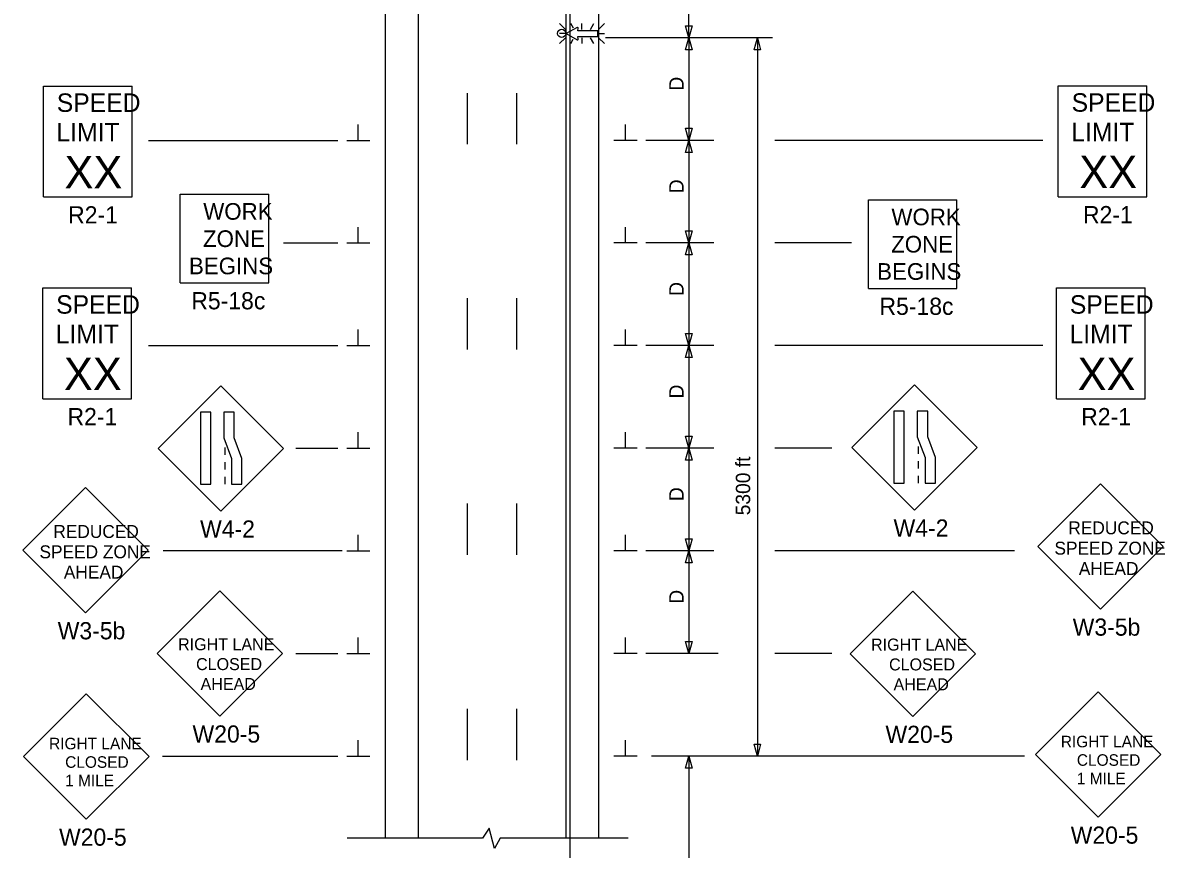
# Model space of a CAD drawing. Extents: x 16247 to 18479, y 5687 to 6964.
# Drawn here: x 16736 to 17293, y 6228 to 6630 of the extents above; entities that cross this region are included whole.
import ezdxf

# ---------------------------------------------------------------- set-up
doc = ezdxf.new("R2010")
doc.units = 0
for name, color, linetype in [('ALI_LEGAL_EX', 7, 'Continuous'), ('PAVT_EDGE_EX', 7, 'Continuous'), ('TRAFFIC_SIGNS_PR', 7, 'Continuous'), ('TYPICAL_TEXT_DIMEN_PR', 7, 'Continuous')]:
    doc.layers.add(name, color=color, linetype=linetype)

msp = doc.modelspace()

# ---------------------------------------------------------------- linework, layer by layer
at = {"layer": 'ALI_LEGAL_EX'}
msp.add_line((17002.72, 6964.07), (17002.72, 6147.1), dxfattribs=at)
for points in [[(16952.72, 6596.22), (16952.72, 6571.22)], [(16976.72, 6596.22), (16976.72, 6571.22)], [(16952.72, 6496.22), (16952.72, 6471.22)], [(16976.72, 6496.22), (16976.72, 6471.22)], [(16952.72, 6396.22), (16952.72, 6371.22)], [(16976.72, 6396.22), (16976.72, 6371.22)], [(16952.72, 6296.22), (16952.72, 6271.22)], [(16976.72, 6296.22), (16976.72, 6271.22)]]:
    msp.add_lwpolyline(points, dxfattribs=at)
at = {"layer": 'PAVT_EDGE_EX'}
for p, q in [((16912.72, 6926.76), (16912.72, 6233.21)), ((16928.72, 6926.76), (16928.72, 6233.21)), ((17000.72, 6926.76), (17000.72, 6233.21)), ((17016.72, 6926.76), (17016.72, 6233.21))]:
    msp.add_line(p, q, dxfattribs=at)
at = {"layer": 'TRAFFIC_SIGNS_PR'}
for p, q in [((16997.71, 6630.03), (17000.53, 6627.21)), ((17000.53, 6625.18), (16997.71, 6625.18)), ((17004.43, 6627.85), (17003.17, 6630.03)), ((17008.61, 6627.21), (17008.61, 6630.03)), ((17012.75, 6627.21), (17014.38, 6630.03)), ((17016.7, 6627.21), (17019.52, 6630.03)), ((17016.7, 6625.18), (17019.52, 6625.18)), ((16997.71, 6620.33), (17000.53, 6623.15)), ((17003.15, 6620.33), (17004.35, 6622.42)), ((17008.61, 6623.15), (17008.61, 6620.33)), ((17014.4, 6620.33), (17012.77, 6623.15)), ((17016.7, 6623.15), (17019.52, 6620.33)), ((16746.2, 6599.56), (16789.4, 6599.56)), ((16746.2, 6545.56), (16746.2, 6599.56)), ((16789.4, 6545.56), (16789.4, 6599.56)), ((17240.76, 6599.64), (17283.96, 6599.64)), ((17240.76, 6545.64), (17240.76, 6599.64)), ((17283.96, 6545.64), (17283.96, 6599.64)), ((16812.81, 6503.68), (16812.81, 6546.88)), ((16812.81, 6546.88), (16856.01, 6546.88)), ((16856.01, 6503.68), (16856.01, 6546.88)), ((16746.2, 6545.56), (16789.4, 6545.56)), ((17148.18, 6500.99), (17148.18, 6544.19)), ((17148.18, 6544.19), (17191.38, 6544.19)), ((17191.38, 6500.99), (17191.38, 6544.19)), ((17240.76, 6545.64), (17283.96, 6545.64)), ((16812.81, 6503.68), (16856.01, 6503.68)), ((16745.89, 6501.23), (16789.09, 6501.23)), ((16745.89, 6447.23), (16745.89, 6501.23)), ((16789.09, 6447.23), (16789.09, 6501.23)), ((17148.18, 6500.99), (17191.38, 6500.99)), ((17239.9, 6501.23), (17283.1, 6501.23)), ((17239.9, 6447.23), (17239.9, 6501.23)), ((17283.1, 6447.23), (17283.1, 6501.23)), ((16832.68, 6453.56), (16802.14, 6423.02)), ((16863.23, 6423.02), (16832.68, 6453.56)), ((17170.66, 6454.04), (17140.11, 6423.49)), ((17201.2, 6423.49), (17170.66, 6454.04)), ((16745.89, 6447.23), (16789.09, 6447.23)), ((17239.9, 6447.23), (17283.1, 6447.23)), ((16802.14, 6423.02), (16832.68, 6392.47)), ((16832.68, 6392.47), (16863.23, 6423.02)), ((16834.53, 6423.57), (16834.53, 6419.97)), ((17140.11, 6423.49), (17170.66, 6392.94)), ((17170.66, 6392.94), (17201.2, 6423.49)), ((17172.5, 6424.04), (17172.5, 6420.44)), ((16834.53, 6416.37), (16834.53, 6412.77)), ((17172.5, 6416.84), (17172.5, 6413.24)), ((16834.53, 6409.17), (16834.53, 6405.57)), ((17172.5, 6409.64), (17172.5, 6406.04)), ((16766.68, 6404), (16736.14, 6373.45)), ((16797.23, 6373.45), (16766.68, 6404)), ((17261.32, 6405.76), (17230.78, 6375.22)), ((17291.87, 6375.22), (17261.32, 6405.76)), ((17230.78, 6375.22), (17261.32, 6344.67)), ((17261.32, 6344.67), (17291.87, 6375.22)), ((16736.14, 6373.45), (16766.68, 6342.9)), ((16766.68, 6342.9), (16797.23, 6373.45)), ((16832.13, 6353.68), (16801.58, 6323.13)), ((16862.68, 6323.13), (16832.13, 6353.68)), ((17169.84, 6353.52), (17139.3, 6322.97)), ((17200.39, 6322.97), (17169.84, 6353.52)), ((16801.58, 6323.13), (16832.13, 6292.58)), ((16832.13, 6292.58), (16862.68, 6323.13)), ((17139.3, 6322.97), (17169.84, 6292.43)), ((17169.84, 6292.43), (17200.39, 6322.97)), ((16767.07, 6303.43), (16736.53, 6272.89)), ((16797.62, 6272.89), (16767.07, 6303.43)), ((17260.1, 6304.41), (17229.56, 6273.87)), ((17290.65, 6273.87), (17260.1, 6304.41)), ((17229.56, 6273.87), (17260.1, 6243.32)), ((17260.1, 6243.32), (17290.65, 6273.87)), ((16736.53, 6272.89), (16767.07, 6242.34)), ((16767.07, 6242.34), (16797.62, 6272.89))]:
    msp.add_line(p, q, dxfattribs=at)
for points in [[(17006.29, 6628.2), (17000.98, 6625.18), (17006.29, 6622.14)], [(17006.79, 6622.5), (17006.56, 6623.8), (17016.28, 6623.8), (17016.28, 6626.54), (17006.56, 6626.54), (17006.79, 6627.84)]]:
    msp.add_lwpolyline(points, dxfattribs=at)
for points in [[(17160.65, 6441.2), (17160.65, 6406.04), (17165.7, 6406.04), (17165.7, 6441.2)], [(17172.05, 6441.2), (17172.05, 6428.62), (17175.81, 6418.62), (17175.81, 6406.04), (17180.87, 6406.04), (17180.87, 6418.62), (17177.11, 6428.62), (17177.11, 6441.2)], [(16822.68, 6440.72), (16822.68, 6405.57), (16827.73, 6405.57), (16827.73, 6440.72)], [(16834.08, 6440.72), (16834.08, 6428.14), (16837.84, 6418.15), (16837.84, 6405.57), (16842.9, 6405.57), (16842.9, 6418.15), (16839.14, 6428.14), (16839.14, 6440.72)]]:
    msp.add_lwpolyline(points, close=True, dxfattribs=at)
msp.add_circle((16998.7, 6625.26), 2, dxfattribs=at)
for centre, start, end in [((17006.45, 6627.9), 350.7308, 118.8916), ((17006.45, 6622.44), 241.4833, 9.9593)]:
    msp.add_arc(centre, 0.341, start, end, dxfattribs=at)
at = {"layer": 'TYPICAL_TEXT_DIMEN_PR'}
for p, q in [((17060.72, 6623.15), (17060.72, 6657.34)), ((17060.72, 6623.15), (17059.15, 6629.01)), ((17059.15, 6629.01), (17060.72, 6629.01)), ((17060.72, 6629.01), (17062.29, 6629.01)), ((17062.29, 6629.01), (17060.72, 6623.15)), ((17101.49, 6623.15), (17020.02, 6623.15)), ((17065.72, 6623.15), (17020.02, 6623.15)), ((17059.15, 6617.29), (17060.72, 6623.15)), ((17060.72, 6623.15), (17060.72, 6573.15)), ((17060.72, 6623.15), (17062.29, 6617.29)), ((17092.53, 6617.29), (17094.11, 6623.15)), ((17094.11, 6623.15), (17095.68, 6617.29)), ((17094.11, 6623.15), (17094.11, 6273.15)), ((17060.72, 6617.29), (17059.15, 6617.29)), ((17062.29, 6617.29), (17060.72, 6617.29)), ((17094.11, 6617.29), (17092.53, 6617.29)), ((17095.68, 6617.29), (17094.11, 6617.29)), ((16899.6, 6573.15), (16899.6, 6580.93)), ((17029.85, 6573.15), (17029.85, 6580.93)), ((17060.72, 6573.15), (17059.15, 6579.01)), ((17059.15, 6579.01), (17060.72, 6579.01)), ((17060.72, 6579.01), (17062.29, 6579.01)), ((17062.29, 6579.01), (17060.72, 6573.15)), ((16797.36, 6573.15), (16889.72, 6573.15)), ((16893.97, 6573.15), (16905.22, 6573.15)), ((17035.47, 6573.15), (17024.22, 6573.15)), ((17072.94, 6573.15), (17039.72, 6573.15)), ((17059.15, 6567.29), (17060.72, 6573.15)), ((17060.72, 6573.15), (17060.72, 6523.15)), ((17060.72, 6573.15), (17062.29, 6567.29)), ((17233.21, 6573.15), (17102.67, 6573.15)), ((17060.72, 6567.29), (17059.15, 6567.29)), ((17062.29, 6567.29), (17060.72, 6567.29)), ((16899.6, 6523.15), (16899.6, 6530.93)), ((17029.85, 6523.15), (17029.85, 6530.93)), ((17060.72, 6523.15), (17059.15, 6529.01)), ((17059.15, 6529.01), (17060.72, 6529.01)), ((17060.72, 6529.01), (17062.29, 6529.01)), ((17062.29, 6529.01), (17060.72, 6523.15)), ((16863.17, 6523.15), (16889.72, 6523.15)), ((16893.97, 6523.15), (16905.22, 6523.15)), ((17035.47, 6523.15), (17024.22, 6523.15)), ((17072.94, 6523.15), (17039.72, 6523.15)), ((17059.15, 6517.29), (17060.72, 6523.15)), ((17060.72, 6523.15), (17060.72, 6473.15)), ((17060.72, 6523.15), (17062.29, 6517.29)), ((17140.04, 6523.15), (17102.67, 6523.15)), ((17060.72, 6517.29), (17059.15, 6517.29)), ((17062.29, 6517.29), (17060.72, 6517.29)), ((16899.6, 6473.15), (16899.6, 6480.93)), ((17029.85, 6473.15), (17029.85, 6480.93)), ((17060.72, 6473.15), (17059.15, 6479.01)), ((17059.15, 6479.01), (17060.72, 6479.01)), ((17060.72, 6479.01), (17062.29, 6479.01)), ((17062.29, 6479.01), (17060.72, 6473.15)), ((16797.36, 6473.15), (16889.72, 6473.15)), ((16893.97, 6473.15), (16905.22, 6473.15)), ((17035.47, 6473.15), (17024.22, 6473.15)), ((17072.94, 6473.15), (17039.72, 6473.15)), ((17059.15, 6467.29), (17060.72, 6473.15)), ((17060.72, 6473.15), (17060.72, 6423.15)), ((17060.72, 6473.15), (17062.29, 6467.29)), ((17233.21, 6473.15), (17102.67, 6473.15)), ((17060.72, 6467.29), (17059.15, 6467.29)), ((17062.29, 6467.29), (17060.72, 6467.29)), ((16899.6, 6423.15), (16899.6, 6430.93)), ((17029.85, 6423.15), (17029.85, 6430.93)), ((17060.72, 6423.15), (17059.15, 6429.01)), ((17059.15, 6429.01), (17060.72, 6429.01)), ((17060.72, 6429.01), (17062.29, 6429.01)), ((17062.29, 6429.01), (17060.72, 6423.15)), ((16869.17, 6423.15), (16889.72, 6423.15)), ((16893.97, 6423.15), (16905.22, 6423.15)), ((17035.47, 6423.15), (17024.22, 6423.15)), ((17072.94, 6423.15), (17039.72, 6423.15)), ((17059.15, 6417.29), (17060.72, 6423.15)), ((17060.72, 6423.15), (17060.72, 6373.15)), ((17060.72, 6423.15), (17062.29, 6417.29)), ((17130.4, 6423.15), (17102.67, 6423.15)), ((17060.72, 6417.29), (17059.15, 6417.29)), ((17062.29, 6417.29), (17060.72, 6417.29)), ((16899.6, 6373.15), (16899.6, 6380.93)), ((17029.85, 6373.15), (17029.85, 6380.93)), ((17060.72, 6373.15), (17059.15, 6379.01)), ((17059.15, 6379.01), (17060.72, 6379.01)), ((17060.72, 6379.01), (17062.29, 6379.01)), ((17062.29, 6379.01), (17060.72, 6373.15)), ((16891.81, 6373.15), (16804.54, 6373.15)), ((16893.97, 6373.15), (16905.22, 6373.15)), ((17035.47, 6373.15), (17024.22, 6373.15)), ((17072.94, 6373.15), (17039.72, 6373.15)), ((17059.15, 6367.29), (17060.72, 6373.15)), ((17060.72, 6373.15), (17060.72, 6323.15)), ((17060.72, 6373.15), (17062.29, 6367.29)), ((17102.67, 6373.15), (17102.67, 6373.15)), ((17219.41, 6373.15), (17102.67, 6373.15)), ((17060.72, 6367.29), (17059.15, 6367.29)), ((17062.29, 6367.29), (17060.72, 6367.29)), ((16899.6, 6323.15), (16899.6, 6330.93)), ((17029.85, 6323.15), (17029.85, 6330.93)), ((17060.72, 6323.15), (17059.15, 6329.01)), ((17059.15, 6329.01), (17060.72, 6329.01)), ((17060.72, 6329.01), (17062.29, 6329.01)), ((17062.29, 6329.01), (17060.72, 6323.15)), ((16869.17, 6323.15), (16889.72, 6323.15)), ((16893.97, 6323.15), (16905.22, 6323.15)), ((17035.47, 6323.15), (17024.22, 6323.15)), ((17075.05, 6323.15), (17039.72, 6323.15)), ((17130.4, 6323.15), (17102.67, 6323.15)), ((16899.6, 6273.15), (16899.6, 6280.93)), ((17029.85, 6273.15), (17029.85, 6280.93)), ((17094.11, 6273.15), (17092.53, 6279.01)), ((17092.53, 6279.01), (17094.11, 6279.01)), ((17094.11, 6279.01), (17095.68, 6279.01)), ((17095.68, 6279.01), (17094.11, 6273.15)), ((16804.18, 6273.15), (16889.72, 6273.15)), ((16893.97, 6273.15), (16905.22, 6273.15)), ((17035.47, 6273.15), (17024.22, 6273.15)), ((17224.3, 6273.15), (17042.57, 6273.15)), ((17059.15, 6267.29), (17060.72, 6273.15)), ((17060.72, 6273.15), (17060.72, 6123.15)), ((17060.72, 6273.15), (17062.29, 6267.29)), ((17060.72, 6267.29), (17059.15, 6267.29)), ((17062.29, 6267.29), (17060.72, 6267.29)), ((16963.32, 6238.01), (16960.07, 6233.21)), ((16966.07, 6228.07), (16963.32, 6238.01)), ((16960.07, 6233.21), (16894.13, 6233.21)), ((16968.81, 6233.21), (16966.07, 6228.07)), ((17031.14, 6233.21), (16968.81, 6233.21))]:
    msp.add_line(p, q, dxfattribs=at)

# ---------------------------------------------------------------- texts
at = {"layer": 'TRAFFIC_SIGNS_PR'}
for s, height, p in [('SPEED', 9, (16752.69, 6587.02)), ('SPEED', 9, (17247.24, 6587.1)), ('LIMIT', 9, (16752.51, 6572.62)), ('LIMIT', 9, (17247.06, 6572.7)), ('XX', 15.785, (16756.45, 6549.78)), ('XX', 15.785, (17251.01, 6549.86)), ('R2-1', 8.37, (16758.21, 6532.69)), ('WORK', 8.119, (16824.06, 6534.47)), ('R2-1', 8.37, (17252.77, 6532.77)), ('WORK', 8.119, (17159.43, 6531.77)), ('ZONE', 8.119, (16823.93, 6521.19)), ('ZONE', 8.119, (17159.3, 6518.49)), ('BEGINS', 8.119, (16817.1, 6507.9)), ('BEGINS', 8.119, (17152.47, 6505.2)), ('SPEED', 9, (16752.38, 6488.7)), ('R5-18c', 8.37, (16818.23, 6490.82)), ('R5-18c', 8.37, (17153.6, 6488.12)), ('SPEED', 9, (17246.39, 6488.7)), ('LIMIT', 9, (16752.2, 6474.3)), ('LIMIT', 9, (17246.21, 6474.3)), ('XX', 15.785, (16756.15, 6451.46)), ('XX', 15.785, (17250.15, 6451.46)), ('R2-1', 8.37, (16757.9, 6434.36)), ('R2-1', 8.37, (17251.91, 6434.36)), ('REDUCED', 6.3, (16751, 6379.42)), ('W4-2', 8.37, (16822.51, 6379.6)), ('W4-2', 8.37, (17160.48, 6380.07)), ('REDUCED', 6.3, (17245.64, 6381.19)), ('SPEED ZONE', 6.3, (16744.24, 6369.52)), ('SPEED ZONE', 6.3, (17238.88, 6371.29)), ('AHEAD', 6.3, (16756.12, 6359.62)), ('AHEAD', 6.3, (17250.76, 6361.39)), ('W3-5b', 8.37, (16753.13, 6330.03)), ('W3-5b', 8.37, (17247.77, 6331.8)), ('RIGHT LANE', 5.85, (16811.79, 6324.7)), ('RIGHT LANE', 5.85, (17149.5, 6324.54)), ('CLOSED', 5.85, (16820.56, 6315.03)), ('CLOSED', 5.85, (17158.27, 6314.87)), ('AHEAD', 5.85, (16822.75, 6305.35)), ('AHEAD', 5.85, (17160.46, 6305.19)), ('W20-5', 8.37, (16818.83, 6279.72)), ('W20-5', 8.37, (17156.54, 6279.56)), ('RIGHT LANE', 5.625, (16748.94, 6276.43)), ('RIGHT LANE', 5.625, (17241.97, 6277.41)), ('CLOSED', 5.625, (17249.8, 6268.41)), ('CLOSED', 5.625, (16756.77, 6267.43)), ('1 MILE', 5.625, (16756.76, 6258.43)), ('1 MILE', 5.625, (17249.79, 6259.41)), ('W20-5', 8.37, (16753.77, 6229.47)), ('W20-5', 8.37, (17246.8, 6230.45))]:
    msp.add_text(s, height=height, dxfattribs=at).set_placement(p)
at = {"layer": 'TYPICAL_TEXT_DIMEN_PR'}
for s, p in [('D', (17058.16, 6597.37)), ('D', (17058.16, 6547.37)), ('D', (17058.16, 6497.37)), ('D', (17058.16, 6447.37)), ('5300 ft', (17090.59, 6390.45)), ('D', (17058.16, 6397.37)), ('D', (17058.16, 6347.37))]:
    msp.add_text(s, height=7, rotation=90, dxfattribs=at).set_placement(p)

doc.saveas('drawing.dxf')
